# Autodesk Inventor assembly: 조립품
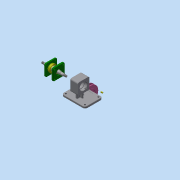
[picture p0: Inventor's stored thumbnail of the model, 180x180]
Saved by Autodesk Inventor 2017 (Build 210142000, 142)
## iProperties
Part Number: 조립품
Material: 일반
Document SubType Name: Assembly
Designer: mrc
Author: mrc
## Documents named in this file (10)
- C:\Users\mrc\Desktop\701106V1015\조립품.iam
- C:\Users\mrc\Desktop\701106V1015\V-벨트풀리.ipt
- C:\Users\mrc\Desktop\701106V1015\너트 M10x1.ipt
- C:\Users\mrc\Desktop\701106V1015\베어링 6004.ipt
- C:\Users\mrc\Desktop\701106V1015\본체.ipt
- C:\Users\mrc\Desktop\701106V1015\볼트 M4.ipt
- C:\Users\mrc\Desktop\701106V1015\오일 실 17 30 5.ipt
- C:\Users\mrc\Desktop\701106V1015\축.ipt
- C:\Users\mrc\Desktop\701106V1015\커버.ipt
- C:\Users\mrc\Desktop\701106V1015\키 5 x 5 x 12.ipt
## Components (1 placed, 1 different names)
1. V-벨트풀리:2
